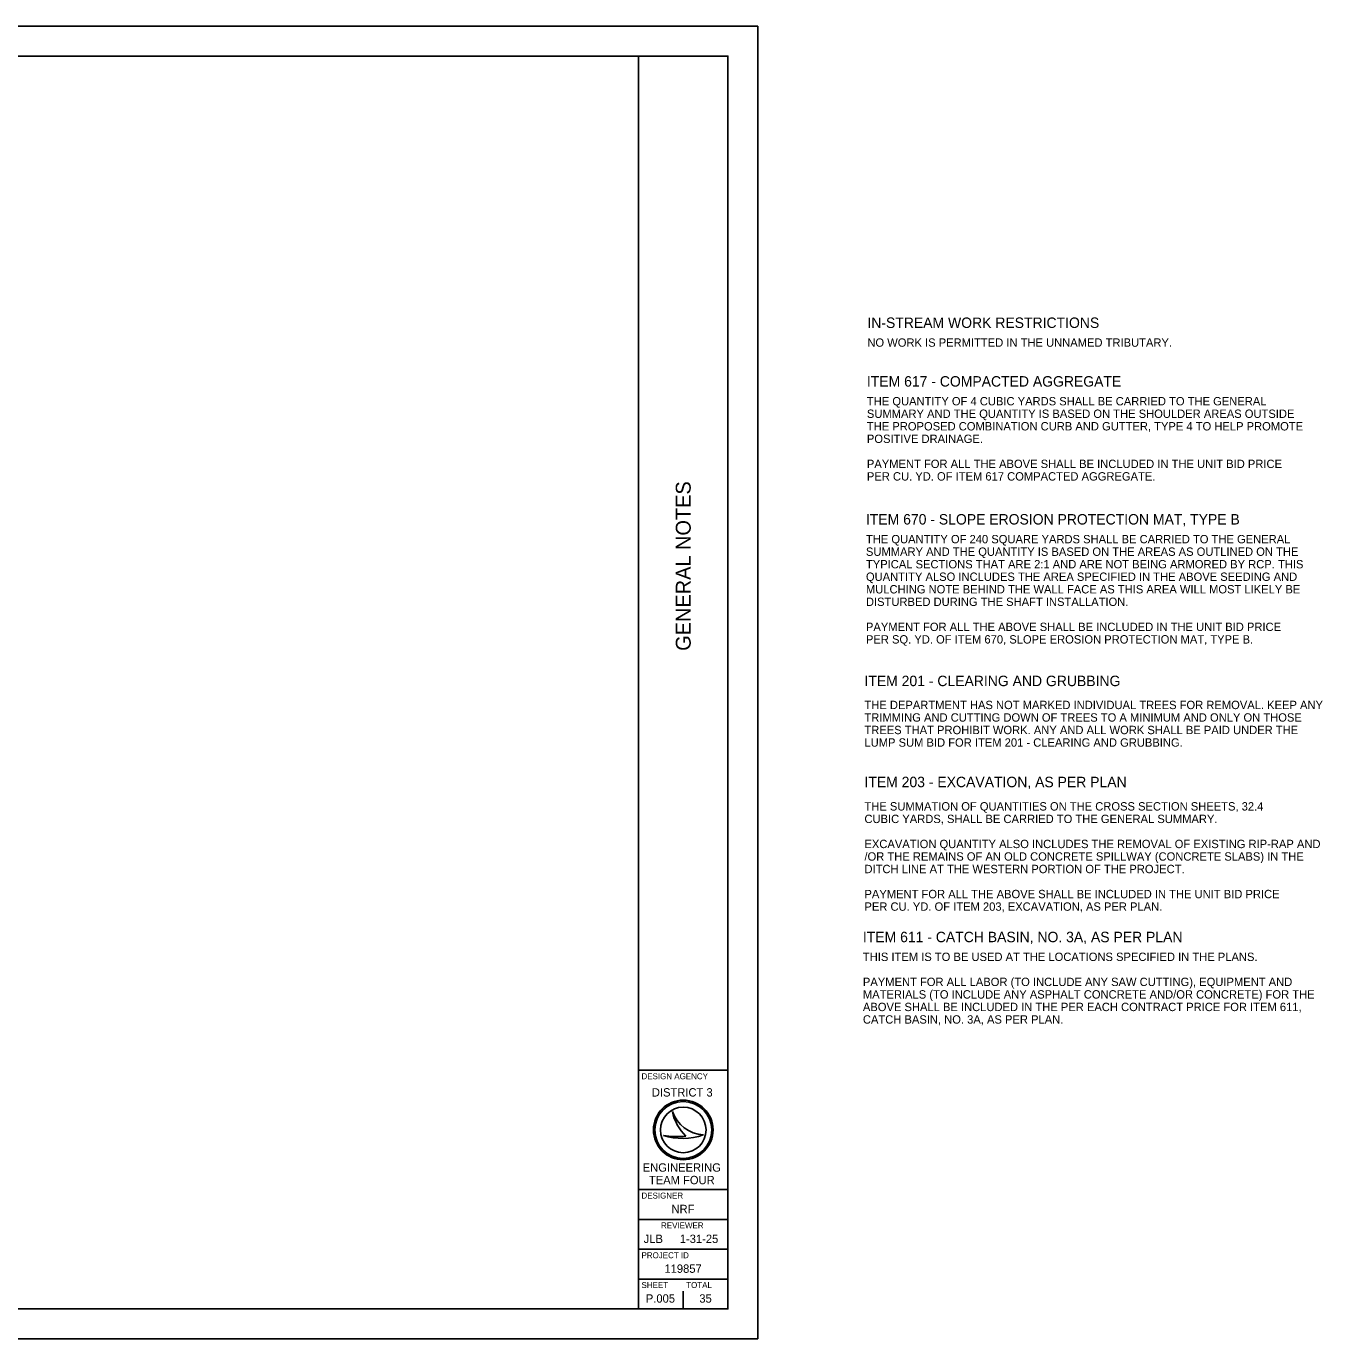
# Model space of a CAD drawing. Extents: x 0 to 43.5, y 0 to 44.1.
# Drawn here: x 21.74 to 43.47, y 0 to 22 of the extents above; entities that cross this region are included whole.
import ezdxf

# ---------------------------------------------------------------- set-up
doc = ezdxf.new("R2010")
doc.units = 0
for name, color, linetype in [('SH_Border', 7, 'Continuous'), ('SH_Cut_Line', 7, 'Continuous'), ('SH_Data', 7, 'Continuous'), ('TX_P_1', 7, 'Continuous')]:
    doc.layers.add(name, color=color, linetype=linetype)

msp = doc.modelspace()

# ---------------------------------------------------------------- linework, layer by layer
at = {"layer": 'SH_Border'}
for p, q in [((32, 0.5), (32, 21.5)), ((32, 4.5), (33.5, 4.5)), ((32, 2.5), (33.5, 2.5)), ((32, 2), (33.5, 2)), ((32, 1.5), (33.5, 1.5)), ((32, 1), (33.5, 1))]:
    msp.add_line(p, q, dxfattribs=at)
msp.add_lwpolyline([(1.5, 21.5), (33.5, 21.5), (33.5, 0.5), (1.5, 0.5)], close=True, dxfattribs=at)
at = {"layer": 'SH_Cut_Line'}
msp.add_lwpolyline([(0, 0), (34, 0), (34, 22), (0, 22)], close=True, dxfattribs=at)
at = {"layer": 'SH_Data'}
for p, q in [((32.567, 3.81), (32.567, 3.81)), ((32.417, 3.41), (32.417, 3.41)), ((32.75, 3.5), (32.75, 3.5)), ((33.087, 3.419), (33.087, 3.419)), ((32.375, 0.675), (32.375, 0.675)), ((32.75, 0.5), (32.75, 0.8))]:
    msp.add_line(p, q, dxfattribs=at)
for radius in [0.5, 0.477, 0.477, 0.382]:
    msp.add_circle((32.75, 3.5), radius, dxfattribs=at)
for centre, radius, start, end in [((33.116, 3.998), 0.58, 198.9257, 198.9319), ((33.347, 3.97), 0.796, 191.6379, 191.6421), ((33.116, 3.998), 0.58, 198.9319, 267.1657), ((33.347, 3.97), 0.796, 191.6421, 226.0947), ((32.739, 4.37), 1.013, 251.4576, 290.0832), ((32.648, 4.654), 1.266, 259.4964, 259.4995), ((32.739, 4.37), 1.013, 251.4527, 251.4576), ((32.648, 4.654), 1.266, 259.4995, 276.6672)]:
    msp.add_arc(centre, radius, start, end, dxfattribs=at)

# ---------------------------------------------------------------- texts
msp.add_text('GENERAL NOTES', height=0.25, rotation=90, dxfattribs=at).set_placement((32.875, 11.531))
for s, height, p in [('DESIGN AGENCY', 0.1, (32.05, 4.35)), ('DISTRICT 3', 0.14, (32.224, 4.06)), ('ENGINEERING', 0.14, (32.071, 2.8)), ('TEAM FOUR', 0.14, (32.175, 2.59)), ('DESIGNER', 0.1, (32.05, 2.35)), ('NRF', 0.14, (32.553, 2.105)), ('REVIEWER', 0.1, (32.378, 1.85)), ('JLB', 0.14, (32.087, 1.605)), ('1-31-25', 0.14, (32.692, 1.605)), ('PROJECT ID', 0.1, (32.05, 1.35)), ('119857', 0.14, (32.435, 1.105)), ('SHEET', 0.1, (32.05, 0.85)), ('TOTAL', 0.1, (32.8, 0.85)), ('P.005', 0.14, (32.123, 0.605)), ('35', 0.14, (33.02, 0.605))]:
    msp.add_text(s, height=height, dxfattribs=at).set_placement(p)
at = {"layer": 'TX_P_1'}
for s, height, p in [('IN-STREAM WORK RESTRICTIONS', 0.175, (35.837, 16.943)), ('NO WORK IS PERMITTED IN THE UNNAMED TRIBUTARY.', 0.14, (35.837, 16.628)), ('ITEM 617 - COMPACTED AGGREGATE', 0.175, (35.829, 15.96)), ('THE QUANTITY OF 4 CUBIC YARDS SHALL BE CARRIED TO THE GENERAL ', 0.14, (35.829, 15.645)), ('SUMMARY AND THE QUANTITY IS BASED ON THE SHOULDER AREAS OUTSIDE ', 0.14, (35.829, 15.435)), ('THE PROPOSED COMBINATION CURB AND GUTTER, TYPE 4 TO HELP PROMOTE', 0.14, (35.829, 15.225)), ('POSITIVE DRAINAGE.', 0.14, (35.829, 15.015)), ('PAYMENT FOR ALL THE ABOVE SHALL BE INCLUDED IN THE UNIT BID PRICE ', 0.14, (35.829, 14.595)), ('PER CU. YD. OF ITEM 617 COMPACTED AGGREGATE.', 0.14, (35.829, 14.385)), ('ITEM 670 - SLOPE EROSION PROTECTION MAT, TYPE B', 0.175, (35.813, 13.648)), ('THE QUANTITY OF 240 SQUARE YARDS SHALL BE CARRIED TO THE GENERAL ', 0.14, (35.813, 13.333)), ('SUMMARY AND THE QUANTITY IS BASED ON THE AREAS AS OUTLINED ON THE ', 0.14, (35.813, 13.123)), ('TYPICAL SECTIONS THAT ARE 2:1 AND ARE NOT BEING ARMORED BY RCP. THIS ', 0.14, (35.813, 12.913)), ('QUANTITY ALSO INCLUDES THE AREA SPECIFIED IN THE ABOVE SEEDING AND  ', 0.14, (35.813, 12.703)), ('MULCHING NOTE BEHIND THE WALL FACE AS THIS AREA WILL MOST LIKELY BE ', 0.14, (35.813, 12.493)), ('DISTURBED DURING THE SHAFT INSTALLATION. ', 0.14, (35.813, 12.283)), ('PAYMENT FOR ALL THE ABOVE SHALL BE INCLUDED IN THE UNIT BID PRICE ', 0.14, (35.813, 11.863)), ('PER SQ. YD. OF ITEM 670, SLOPE EROSION PROTECTION MAT, TYPE B.', 0.14, (35.813, 11.653)), ('ITEM 201 - CLEARING AND GRUBBING', 0.175, (35.788, 10.939)), ('THE DEPARTMENT HAS NOT MARKED INDIVIDUAL TREES FOR REMOVAL. KEEP ANY ', 0.14, (35.788, 10.554)), ('TRIMMING AND CUTTING DOWN OF TREES TO A MINIMUM AND ONLY ON THOSE ', 0.14, (35.788, 10.344)), ('TREES THAT PROHIBIT WORK. ANY AND ALL WORK SHALL BE PAID UNDER THE ', 0.14, (35.788, 10.134)), ('LUMP SUM BID FOR ITEM 201 - CLEARING AND GRUBBING.', 0.14, (35.788, 9.924)), ('ITEM 203 - EXCAVATION, AS PER PLAN', 0.175, (35.788, 9.245)), ('THE SUMMATION OF QUANTITIES ON THE CROSS SECTION SHEETS, 32.4 ', 0.14, (35.788, 8.854)), ('CUBIC YARDS, SHALL BE CARRIED TO THE GENERAL SUMMARY.', 0.14, (35.788, 8.644)), ('EXCAVATION QUANTITY ALSO INCLUDES THE REMOVAL OF EXISTING RIP-RAP AND', 0.14, (35.788, 8.224)), ('/OR THE REMAINS OF AN OLD CONCRETE SPILLWAY (CONCRETE SLABS) IN THE  ', 0.14, (35.788, 8.014)), ('DITCH LINE AT THE WESTERN PORTION OF THE PROJECT.  ', 0.14, (35.788, 7.804)), ('PAYMENT FOR ALL THE ABOVE SHALL BE INCLUDED IN THE UNIT BID PRICE ', 0.14, (35.788, 7.384)), ('PER CU. YD. OF ITEM 203, EXCAVATION, AS PER PLAN.', 0.14, (35.788, 7.174)), ('ITEM 611 - CATCH BASIN, NO. 3A, AS PER PLAN', 0.175, (35.762, 6.647)), ('THIS ITEM IS TO BE USED AT THE LOCATIONS SPECIFIED IN THE PLANS. ', 0.14, (35.762, 6.332)), ('PAYMENT FOR ALL LABOR (TO INCLUDE ANY SAW CUTTING), EQUIPMENT AND ', 0.14, (35.762, 5.912)), ('MATERIALS (TO INCLUDE ANY ASPHALT CONCRETE AND/OR CONCRETE) FOR THE ', 0.14, (35.762, 5.702)), ('ABOVE SHALL BE INCLUDED IN THE PER EACH CONTRACT PRICE FOR ITEM 611, ', 0.14, (35.762, 5.492)), ('CATCH BASIN, NO. 3A, AS PER PLAN. ', 0.14, (35.762, 5.282))]:
    msp.add_text(s, height=height, dxfattribs=at).set_placement(p)

doc.saveas('drawing.dxf')
